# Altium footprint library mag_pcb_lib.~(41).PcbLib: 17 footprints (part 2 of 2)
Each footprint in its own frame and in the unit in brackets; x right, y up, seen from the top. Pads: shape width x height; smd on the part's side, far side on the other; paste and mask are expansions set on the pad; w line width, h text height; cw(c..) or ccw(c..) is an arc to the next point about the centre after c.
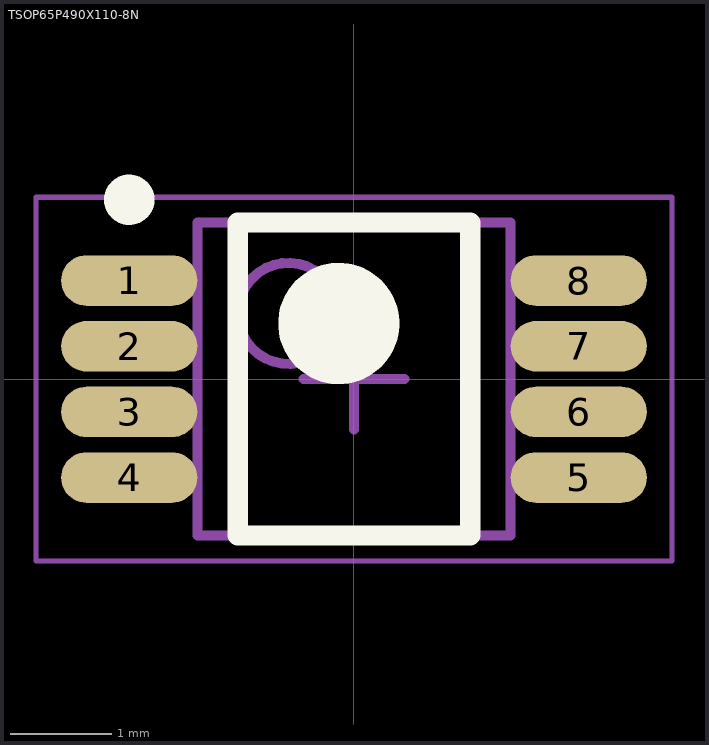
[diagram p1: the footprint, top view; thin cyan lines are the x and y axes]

## TSOP65P490X110-8N [mm] "TSOP, 8-Leads, Body 3.00x3.00mm, Pitch 0.65mm, IPC Medium Density"
height 1.1
pads (8):
  oval 1.35x0.5 smd: 1(-2.225,0.975) 2(-2.225,0.325) 3(-2.225,-0.325) 4(-2.225,-0.975) 5(2.225,-0.975) 6(2.225,-0.325) 7(2.225,0.325) 8(2.225,0.975)
Top Overlay:
  circle w0.25: c-2.225,1.775 r0.125
  circle w0.6: c-0.15,0.55 r0.3
  lines w0.2: -1.15,-1.55 -1.15,1.55 1.15,1.55 1.15,-1.55 -1.15,-1.55
Mechanical 13:
  circle w0.1: c-0.65,0.65 r0.5
  lines w0.1: -1.55,-1.55 -1.55,1.55 1.55,1.55 1.55,-1.55 -1.55,-1.55
Mechanical 15:
  lines w0.05: -3.15,-1.8 -3.15,1.8 3.15,1.8 3.15,-1.8 -3.15,-1.8
  lines w0.1: -0.5,0 0.5,0 ; 0,-0.5 0,0.5
3D body: height 1.1, standoff 0.25, extent -1.55,-1.55 1.55,1.55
